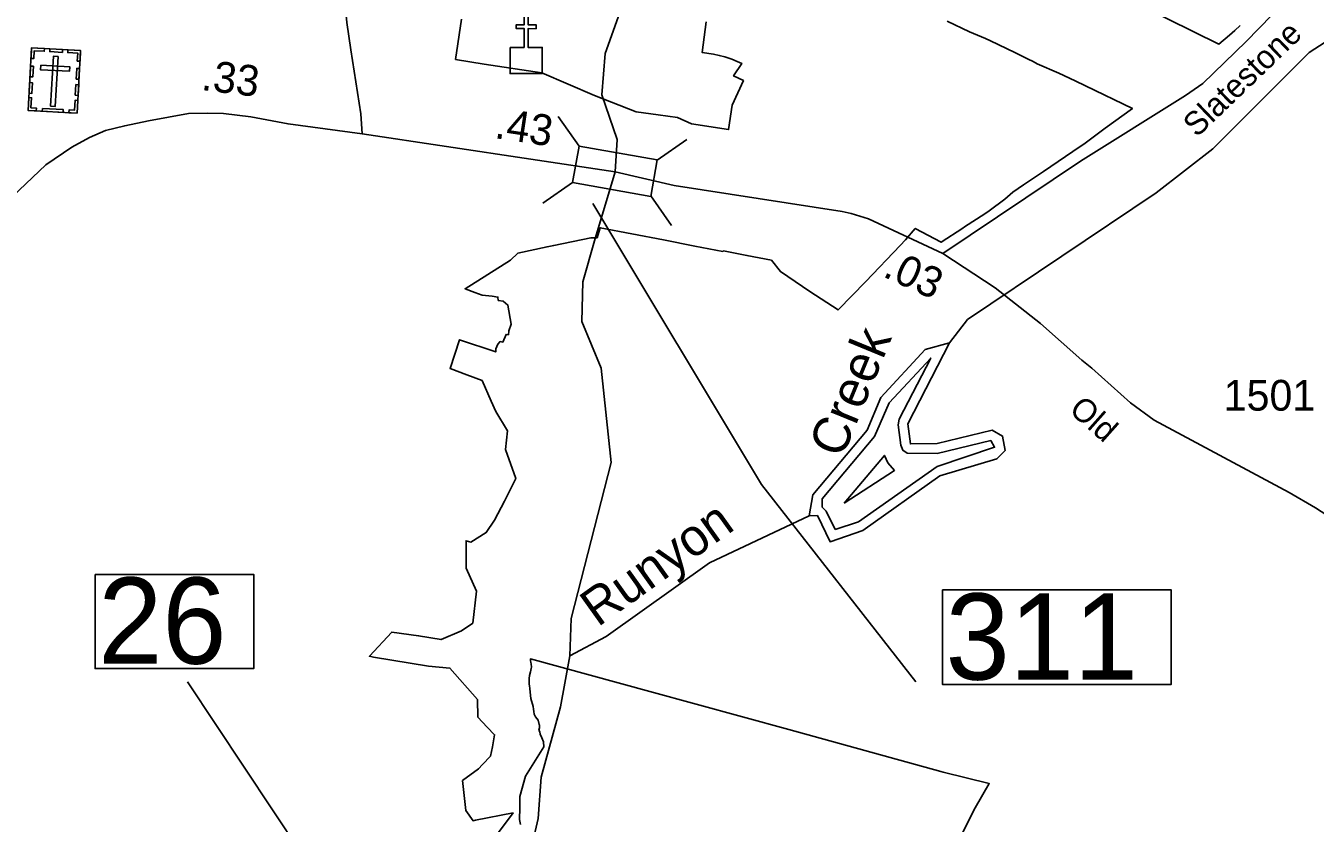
# Model space of a CAD drawing. Extents: x 2532689 to 2764727, y 536648 to 732970.
# Drawn here: x 2586089 to 2591324, y 659937 to 663175 of the extents above; entities that cross this region are included whole.
import ezdxf

# ---------------------------------------------------------------- set-up
doc = ezdxf.new("R2010")
doc.units = 0
for name, color, linetype in [('Exist Boundary Political City Limit New', 7, 'Continuous'), ('Exist Cultural Cemetery CELL', 7, 'Continuous'), ('Exist Cultural Church CELL', 7, 'Continuous'), ('Exist Hydrographic Buffer Line', 7, 'Continuous'), ('Exist Hydrographic Creek Single Shore', 7, 'Continuous'), ('Exist Hydrographic Creek Single Shore Label', 7, 'Continuous'), ('Exist Hydrographic Pond Under 1500 Sq Ft', 7, 'Continuous'), ('Exist Road Primary Interstate Shield CELL', 7, 'Continuous'), ('Exist Road Primary US Structure Standard Bridge Number Label', 7, 'Continuous'), ('Exist Road Secondary Mileage Hundredths English Label', 7, 'Continuous'), ('Exist Road Secondary Structure Standard Bridge CELL', 7, 'Continuous'), ('Exist Road Secondary Structure Standard Bridge Number Label', 7, 'Continuous'), ('Exist Road Secondary Type 51 Attributed', 7, 'Continuous'), ('Exist Road Secondary Type 51 Label', 7, 'Continuous'), ('Exist Road Secondary Type 51 Number Label', 7, 'Continuous'), ('Map Preparation Boundary City Limit Buffer Line', 7, 'Continuous')]:
    doc.layers.add(name, color=color, linetype=linetype)

# ---------------------------------------------------------------- blocks, each defined once
blk = doc.blocks.new('Exist Cultural Church')
at = {"layer": 'Exist Road Primary Interstate Shield CELL'}
blk.add_lwpolyline([(-65.2, 26.9), (-8.3, 27), (-8.3, 103.2), (-40.3, 103.2), (-40.3, 119.2), (-8.3, 119.2), (-8.3, 179.3), (7.7, 179.3), (7.7, 119.2), (39.7, 119.2), (39.7, 103.2), (7.7, 103.2), (7.7, 27), (65.4, 26.9), (65.4, -79.5), (-65.2, -79.5)], close=True, dxfattribs=at)

msp = doc.modelspace()

# ---------------------------------------------------------------- linework, layer by layer
at = {"layer": 'Exist Boundary Political City Limit New'}
for points in [[(2591018.8, 663176.4), (2590996.8, 663156.7), (2590975.2, 663137.7), (2590932.5, 663101.2), (2590112.2, 663507.2)], [(2587857, 663202.4), (2587833.5, 663038.6)], [(2587833.5, 663038.6), (2587949.5, 663020.1), (2588183, 662984.9), (2588397, 662892.9), (2588567, 662826.6), (2588655.8, 662813.9), (2588734.5, 662802.8), (2588791.5, 662776.7), (2588942, 662754), (2588956.5, 662853.2), (2588979.5, 662903.4), (2589002, 662952.9), (2588962.2, 662972.1), (2588995.5, 663022.7), (2588977.2, 663031.1), (2588954.8, 663039.9), (2588926.8, 663049.2), (2588904.2, 663055.2), (2588881, 663060.1), (2588834.5, 663067.5), (2588850.8, 663190.9)], [(2589829, 663194), (2589919.8, 663151.4), (2589984.5, 663123.6), (2590005, 663114.6), (2590104.2, 663066.6), (2590158.5, 663040.2), (2590179, 663030.8), (2590194.5, 663021.1), (2590282.2, 662982.8), (2590348.8, 662951.9), (2590391, 662931.5)], [(2590391, 662931.5), (2590581.2, 662839.7), (2590471, 662759), (2590389.2, 662699.2), (2590339.2, 662665.2), (2590220, 662584.1), (2590139.5, 662529.2), (2590096.5, 662500), (2590063, 662471), (2590000, 662423.4), (2589982.5, 662411.4), (2589900.2, 662358.6), (2589892.8, 662353.8), (2589804.8, 662296.6), (2589699.5, 662352.6), (2589659.5, 662305.9), (2589637.8, 662283.1), (2589499, 662136.9), (2589386.5, 662021.4), (2589272, 662096.8), (2589152.2, 662177.1), (2589116, 662223.6), (2589016.5, 662242.9), (2588921, 662261.2), (2588918.5, 662259.2), (2588805, 662280.7), (2588677.5, 662305.6), (2588420.8, 662354.9), (2588407.8, 662314.4), (2588382.5, 662313.8), (2588232.2, 662283.6), (2588205, 662277.8), (2588086.5, 662252.2), (2588057, 662224.2), (2587871.8, 662107.8), (2587911.2, 662092.5), (2587941, 662081.7), (2587982.5, 662077.2), (2588005.2, 662073.4), (2588007, 662060.2), (2588026.8, 662056.4), (2588046, 662041.3), (2588059.2, 661963.9), (2588049.5, 661936.4), (2588048.2, 661920.9), (2588038.2, 661922.3), (2588025.5, 661890.8), (2588014.2, 661893.2), (2588004.8, 661883), (2587996.8, 661863.9), (2587996.5, 661851), (2587849.5, 661900.1), (2587811.5, 661783), (2587879, 661758.4), (2587941, 661735.5), (2587978.2, 661651.2), (2587997.5, 661608.3), (2588044, 661531), (2588036.8, 661454.1), (2588078, 661337.2), (2588031.5, 661245.2), (2587992, 661167.4), (2587958.2, 661117.2), (2587896, 661078.9), (2587876.2, 661084.2), (2587876.5, 660972.1), (2587918.5, 660879.1), (2587903, 660749.7), (2587857.8, 660718.6), (2587774.8, 660682.4), (2587683.2, 660698.2), (2587574.2, 660713.2), (2587484, 660614.7), (2587500, 660611.4), (2587723.2, 660574.9), (2587810.2, 660566.6), (2587922.2, 660439.2), (2587923.8, 660367.9), (2587962, 660327.3), (2587991.5, 660295.9), (2587982.8, 660246.4), (2587975.5, 660209.3), (2587943, 660175.2), (2587927, 660158.3), (2587861.2, 660109.8), (2587874.5, 659988.9), (2587904.5, 659947.1), (2587914.8, 659949.1), (2588067.2, 659978.9), (2587888.8, 659738.9)], [(2588097.5, 659931.9), (2588093, 659951.8), (2588094, 660000), (2588094.8, 660045.6), (2588117.5, 660127.6), (2588117.8, 660128.1), (2588192, 660246.4), (2588189.8, 660267.5), (2588184.2, 660283.1), (2588176.5, 660298.2), (2588175, 660308.2), (2588171.5, 660314.1), (2588174, 660323.9), (2588173.8, 660335.4), (2588173, 660338.4), (2588168.8, 660355.4), (2588158.5, 660369.2), (2588152.8, 660379.6), (2588151, 660389.9), (2588150.5, 660400.2), (2588148.2, 660411.2), (2588139.2, 660443.2), (2588138.2, 660454.9), (2588134.8, 660484.5), (2588133.2, 660494.5), (2588132.2, 660502.1), (2588131.8, 660512.4), (2588132, 660524.4), (2588133.5, 660536.8), (2588137.5, 660551.2), (2588141, 660564.7), (2588141.5, 660571.2), (2588140.5, 660584), (2588139.5, 660589.1), (2588138, 660597.3), (2588137.5, 660603.9), (2588621.8, 660471.9), (2589185.8, 660317.1), (2589804, 660147.2), (2589813.5, 660144.6), (2590000, 660098.1), (2589943, 660000), (2589883.8, 659881.6)]]:
    msp.add_lwpolyline(points, dxfattribs=at)
at = {"layer": 'Exist Cultural Cemetery CELL'}
for points in [[(2586112.3, 663086), (2586311, 663074.8), (2586296.8, 662820.6), (2586098, 662831.7)], [(2586109.8, 663042.7), (2586121.2, 663042.1), (2586123, 663074.2), (2586163.5, 663071.9), (2586164.1, 663083), (2586112.3, 663086)], [(2586186.2, 663081.8), (2586238, 663078.9), (2586237.3, 663067.5), (2586185.6, 663070.4)], [(2586308.7, 663031.5), (2586297.4, 663032.1), (2586299.2, 663064.3), (2586258.7, 663066.5), (2586259.3, 663077.7), (2586311.1, 663074.8)], [(2586105.7, 662968.7), (2586108.1, 663011.9), (2586119.5, 663011.3), (2586117, 662968)], [(2586149.2, 663015.7), (2586148.2, 662997.1), (2586265.7, 662990.5), (2586266.8, 663009.1)], [(2586219.5, 663050.6), (2586200.8, 663051.6), (2586189.5, 662849.2), (2586208.1, 662848.1)], [(2586293.2, 662959.2), (2586295.6, 663002.4), (2586307, 663001.8), (2586304.6, 662958.5)], [(2586101.9, 662901.6), (2586104.3, 662944.8), (2586115.7, 662944.2), (2586113.3, 662900.9)], [(2586289.5, 662893.4), (2586291.9, 662936.6), (2586303.3, 662936), (2586300.8, 662892.7)], [(2586131, 662829.9), (2586131.7, 662841.4), (2586109.7, 662842.6), (2586112, 662883), (2586100.9, 662883.6), (2586098, 662831.8)], [(2586263.7, 662822.4), (2586264.3, 662833.9), (2586286.3, 662832.7), (2586288.6, 662873), (2586299.7, 662872.4), (2586296.8, 662820.6)], [(2586156, 662840), (2586240.7, 662835.2), (2586240.1, 662823.8), (2586155.4, 662828.6)]]:
    msp.add_lwpolyline(points, close=True, dxfattribs=at)
at = {"layer": 'Exist Hydrographic Buffer Line'}
for points in [[(2589374.7, 661129.4), (2589338.2, 661204.1), (2589322.2, 661221.1), (2589321.8, 661253.7), (2589534.9, 661507.1), (2589593.5, 661644.5), (2589762.9, 661825.6), (2589634.7, 661577.6), (2589630.6, 661554.4), (2589640.5, 661472.7), (2589649.5, 661451.9), (2589666.5, 661440), (2589788.7, 661438.7), (2590006.1, 661491), (2590021.5, 661463.7), (2589788.1, 661386.2), (2589468.9, 661161), (2589374.7, 661129.4)], [(2589411.7, 661236.1), (2589574.9, 661430.4), (2589588.4, 661400.5), (2589615.1, 661369.7), (2589411.7, 661236.1)]]:
    msp.add_lwpolyline(points, dxfattribs=at)
at = {"layer": 'Exist Hydrographic Creek Single Shore'}
for points in [[(2588297.4, 660617.3), (2588302.3, 660768.4), (2588465.3, 661402.2), (2588424.3, 661784.6), (2588345.4, 661975.1), (2588350.3, 662136.2), (2588397.3, 662302.3), (2588481.6, 662582.7), (2588489.3, 662713.1), (2588427.2, 662894.5), (2588440.3, 663062.4), (2588575.2, 663438.8), (2588572.2, 663596.4), (2588537.3, 663690.1), (2588531.2, 663972.2), (2588626.3, 664215.7)], [(2589839.4, 661887.8), (2589912.4, 661982.7), (2590677.2, 662496.4), (2590907.3, 662676.4), (2591299.4, 663066.5), (2591406.4, 663136.5), (2591664.4, 663150.2), (2591998.4, 663114.5), (2592440.3, 663122.5), (2592657.4, 663078.8), (2593288.4, 662799)], [(2588297.4, 660617.3), (2588445.2, 660695.4), (2588864.4, 660994.8), (2589269.3, 661185.2)], [(2587246.3, 658929.8), (2587512.1, 659167.6), (2587892.2, 659599.5), (2588122.3, 659756.6), (2588168.2, 659955.4), (2588181.3, 660123.4), (2588259.3, 660408.9), (2588297.4, 660617.3)]]:
    msp.add_lwpolyline(points, dxfattribs=at)
at = {"layer": 'Exist Hydrographic Pond Under 1500 Sq Ft'}
for points in [[(2589269.3, 661185.2), (2589284.3, 661271.1), (2589504.3, 661532.8), (2589559.3, 661666.4), (2589739.3, 661860.9), (2589839.4, 661887.8)], [(2589269.3, 661185.2), (2589302.4, 661186.5), (2589354.2, 661080.3), (2589487.3, 661125), (2589799.4, 661347.8), (2590031.3, 661416.3), (2590064.3, 661450.4), (2590054.3, 661509.1), (2590012.2, 661533.7), (2589788.3, 661478.7), (2589680.3, 661477.6), (2589670.2, 661559.3), (2589839.4, 661887.8)]]:
    msp.add_lwpolyline(points, dxfattribs=at)
at = {"layer": 'Exist Road Primary US Structure Standard Bridge Number Label'}
msp.add_line((2587530.9, 659330.3), (2586744.7, 660511.2), dxfattribs=at)
msp.add_lwpolyline([(2586370, 660947.1), (2587014.2, 660947.1), (2587014.2, 660564.8), (2586370, 660564.8)], close=True, dxfattribs=at)
at = {"layer": 'Exist Road Secondary Structure Standard Bridge CELL'}
for p, q in [((2588250.4, 662807.6), (2588334.6, 662686.9)), ((2588651.8, 662630), (2588772.4, 662714.3)), ((2588187.7, 662454.5), (2588308.4, 662538.7)), ((2588626.1, 662485.1), (2588710.4, 662364.5))]:
    msp.add_line(p, q, dxfattribs=at)
msp.add_lwpolyline([(2588334.6, 662686.9), (2588651.9, 662630.7), (2588625.6, 662482.5), (2588308.4, 662538.7)], close=True, dxfattribs=at)
at = {"layer": 'Exist Road Secondary Structure Standard Bridge Number Label'}
msp.add_lwpolyline([(2588391, 662454.3), (2589075.2, 661312.3), (2589701.5, 660511.2)], dxfattribs=at)
msp.add_lwpolyline([(2589810.2, 660884.4), (2590739.2, 660884.4), (2590739.2, 660500.3), (2589810.2, 660500.3)], close=True, dxfattribs=at)
at = {"layer": 'Exist Road Secondary Type 51 Attributed'}
for points in [[(2587453.8, 662736.7), (2587448.5, 662817.3), (2587408.1, 663078), (2587392, 663188.2), (2587381.2, 663303.8), (2587378.5, 663432.8), (2587381.2, 663553.8), (2587389.3, 663750), (2587443.1, 664072.5), (2587523.7, 664513.3), (2587601.4, 665059.3), (2587687.8, 665949.9), (2587753.4, 666571.2), (2587770.7, 666688.6), (2587805.2, 666774.9), (2587846.6, 666861.2), (2587908.8, 666964.7), (2587991.7, 667071.7), (2588102.2, 667178.7), (2588233.4, 667251.2), (2588789.4, 667444.5), (2588924.1, 667479), (2589081, 667502.4)], [(2594446.7, 664901.8), (2594229.1, 664875.6), (2594045.3, 664865.9), (2593584, 664817), (2593275.4, 664744.7), (2593150.3, 664702.2), (2593074.7, 664689), (2593017, 664671.9), (2592059.2, 664146.9), (2591874.5, 663965.4), (2591043.3, 663111), (2590866.6, 662941.6), (2590797.4, 662892.2), (2590370.8, 662625.7), (2589812.1, 662250.8)], [(2587453.8, 662736.7), (2587153.4, 662776.9), (2587001.6, 662805.1), (2586890.8, 662819.1), (2586828.1, 662820.2), (2586748.6, 662818.9), (2586586.9, 662789.5), (2586490.1, 662769.3), (2586411.9, 662750.5), (2586346.6, 662722.3), (2586276.1, 662682.6), (2586170.3, 662610.4), (2585842, 662301.3), (2585615.3, 662074.1)], [(2588481.6, 662582.7), (2587453.8, 662736.7)], [(2589812.1, 662250.8), (2589509.3, 662390.9), (2589439.8, 662412.5), (2589402.7, 662420.7), (2588720.4, 662527.4), (2588481.6, 662582.7)], [(2595381.8, 659644.9), (2594972.4, 659811.5), (2594871.5, 659851.4), (2594068.7, 660191.9), (2593983.5, 660244.3), (2593878.6, 660298.1), (2593616.7, 660491.1), (2593420.1, 660619.4), (2593347.5, 660651.9), (2593274.8, 660696.6), (2593008.9, 660793.2), (2592900.4, 660811.1), (2592381.2, 660863), (2591938.2, 660922.2), (2591612, 661032.1), (2591324.1, 661218.4), (2591217.2, 661280.4), (2590669.2, 661573.7), (2590573.8, 661643.8), (2590417, 661784.8), (2590376.6, 661818), (2590208.5, 661966.7), (2590024.6, 662111), (2589812.1, 662250.8)]]:
    msp.add_lwpolyline(points, dxfattribs=at)
at = {"layer": 'Map Preparation Boundary City Limit Buffer Line'}
for points in [[(2591018.8, 663176.4), (2590996.8, 663156.7), (2590975.2, 663137.7), (2590932.5, 663101.2), (2590112.2, 663507.2)], [(2587857, 663202.4), (2587833.5, 663038.6)], [(2587833.5, 663038.6), (2587949.5, 663020.1), (2588183, 662984.9), (2588397, 662892.9), (2588567, 662826.6), (2588655.8, 662813.9), (2588734.5, 662802.8), (2588791.5, 662776.7), (2588942, 662754), (2588956.5, 662853.2), (2588979.5, 662903.4), (2589002, 662952.9), (2588962.2, 662972.1), (2588995.5, 663022.7), (2588977.2, 663031.1), (2588954.8, 663039.9), (2588926.8, 663049.2), (2588904.2, 663055.2), (2588881, 663060.1), (2588834.5, 663067.5), (2588850.8, 663190.9)], [(2589829, 663194), (2589919.8, 663151.4), (2589984.5, 663123.6), (2590005, 663114.6), (2590104.2, 663066.6), (2590158.5, 663040.2), (2590179, 663030.8), (2590194.5, 663021.1), (2590282.2, 662982.8), (2590348.8, 662951.9), (2590391, 662931.5)], [(2590391, 662931.5), (2590581.2, 662839.7), (2590471, 662759), (2590389.2, 662699.2), (2590339.2, 662665.2), (2590220, 662584.1), (2590139.5, 662529.2), (2590096.5, 662500), (2590063, 662471), (2590000, 662423.4), (2589982.5, 662411.4), (2589900.2, 662358.6), (2589892.8, 662353.8), (2589804.8, 662296.6), (2589699.5, 662352.6), (2589659.5, 662305.9), (2589637.8, 662283.1), (2589499, 662136.9), (2589386.5, 662021.4), (2589272, 662096.8), (2589152.2, 662177.1), (2589116, 662223.6), (2589016.5, 662242.9), (2588921, 662261.2), (2588918.5, 662259.2), (2588805, 662280.7), (2588677.5, 662305.6), (2588420.8, 662354.9), (2588407.8, 662314.4), (2588382.5, 662313.8), (2588232.2, 662283.6), (2588205, 662277.8), (2588086.5, 662252.2), (2588057, 662224.2), (2587871.8, 662107.8), (2587911.2, 662092.5), (2587941, 662081.7), (2587982.5, 662077.2), (2588005.2, 662073.4), (2588007, 662060.2), (2588026.8, 662056.4), (2588046, 662041.3), (2588059.2, 661963.9), (2588049.5, 661936.4), (2588048.2, 661920.9), (2588038.2, 661922.3), (2588025.5, 661890.8), (2588014.2, 661893.2), (2588004.8, 661883), (2587996.8, 661863.9), (2587996.5, 661851), (2587849.5, 661900.1), (2587811.5, 661783), (2587879, 661758.4), (2587941, 661735.5), (2587978.2, 661651.2), (2587997.5, 661608.3), (2588044, 661531), (2588036.8, 661454.1), (2588078, 661337.2), (2588031.5, 661245.2), (2587992, 661167.4), (2587958.2, 661117.2), (2587896, 661078.9), (2587876.2, 661084.2), (2587876.5, 660972.1), (2587918.5, 660879.1), (2587903, 660749.7), (2587857.8, 660718.6), (2587774.8, 660682.4), (2587683.2, 660698.2), (2587574.2, 660713.2), (2587484, 660614.7), (2587500, 660611.4), (2587723.2, 660574.9), (2587810.2, 660566.6), (2587922.2, 660439.2), (2587923.8, 660367.9), (2587962, 660327.3), (2587991.5, 660295.9), (2587982.8, 660246.4), (2587975.5, 660209.3), (2587943, 660175.2), (2587927, 660158.3), (2587861.2, 660109.8), (2587874.5, 659988.9), (2587904.5, 659947.1), (2587914.8, 659949.1), (2588067.2, 659978.9), (2587888.8, 659738.9)], [(2588097.5, 659931.9), (2588093, 659951.8), (2588094, 660000), (2588094.8, 660045.6), (2588117.5, 660127.6), (2588117.8, 660128.1), (2588192, 660246.4), (2588189.8, 660267.5), (2588184.2, 660283.1), (2588176.5, 660298.2), (2588175, 660308.2), (2588171.5, 660314.1), (2588174, 660323.9), (2588173.8, 660335.4), (2588173, 660338.4), (2588168.8, 660355.4), (2588158.5, 660369.2), (2588152.8, 660379.6), (2588151, 660389.9), (2588150.5, 660400.2), (2588148.2, 660411.2), (2588139.2, 660443.2), (2588138.2, 660454.9), (2588134.8, 660484.5), (2588133.2, 660494.5), (2588132.2, 660502.1), (2588131.8, 660512.4), (2588132, 660524.4), (2588133.5, 660536.8), (2588137.5, 660551.2), (2588141, 660564.7), (2588141.5, 660571.2), (2588140.5, 660584), (2588139.5, 660589.1), (2588138, 660597.3), (2588137.5, 660603.9), (2588621.8, 660471.9), (2589185.8, 660317.1), (2589804, 660147.2), (2589813.5, 660144.6), (2590000, 660098.1), (2589943, 660000), (2589883.8, 659881.6)]]:
    msp.add_lwpolyline(points, dxfattribs=at)

# ---------------------------------------------------------------- block references
at = {"layer": 'Exist Cultural Church CELL', "rotation": -0.05998015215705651}
msp.add_blockref('Exist Cultural Church', (2588120.2, 663060.6), dxfattribs=at)

# ---------------------------------------------------------------- texts
at = {"layer": 'Exist Hydrographic Creek Single Shore Label'}
for s, rotation, p in [('Creek', 67.6398, (2589402.5, 661414.7)), ('Runyon', 35.5331, (2588410.7, 660731.2))]:
    msp.add_text(s, height=150, rotation=rotation, dxfattribs=at).set_placement(p)
at = {"layer": 'Exist Road Primary US Structure Standard Bridge Number Label'}
msp.add_text('26', height=350, dxfattribs=at).set_placement((2586382.6, 660584.6))
at = {"layer": 'Exist Road Secondary Mileage Hundredths English Label'}
for s, rotation, p in [('.33', 352.8983, (2586797.8, 662915.1)), ('.43', 351.4805, (2587988.3, 662719.8)), ('.03', 335.1738, (2589563.4, 662159.3))]:
    msp.add_text(s, height=125, rotation=rotation, dxfattribs=at).set_placement(p)
at = {"layer": 'Exist Road Secondary Structure Standard Bridge Number Label'}
msp.add_text('311', height=350, dxfattribs=at).set_placement((2589822.8, 660520))
at = {"layer": 'Exist Road Secondary Type 51 Label'}
for s, rotation, p in [('Slatestone', 43.786, (2590843, 662719.2)), ('Old', 318.5023, (2590319.7, 661609.2))]:
    msp.add_text(s, height=95, rotation=rotation, dxfattribs=at).set_placement(p)
at = {"layer": 'Exist Road Secondary Type 51 Number Label'}
msp.add_text('1501', height=125, rotation=359.94, dxfattribs=at).set_placement((2590951.8, 661612.6))

doc.saveas('drawing.dxf')
